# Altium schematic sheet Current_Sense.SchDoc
size 431 x 279 mm; Date: Not shown in title block; ApprovedBy: Not shown in title block; CheckedBy: Not shown in title block; Author: Not shown in title block; CompanyName: Not shown in title block; Engineer: Not shown in title block; Organization: Not shown in title block; Address1: Not shown in title block; Address2: Not shown in title block; Address3: Not shown in title block; Address4: Not shown in title block; DocumentNumber: 1; Revision: Use project parameter SCH_Rev; SheetNumber: 2; SheetTotal: 3; PageSetup: Record=PageOptions¦CenterHorizontal=True¦CenterVertical=True¦PrintScale=1.00¦XCorrection=1.00¦YCorrection=1.00¦PrintKind=0¦BorderSize=5000000¦LeftOffset=0¦BottomOffset=0¦Orientation=2¦PaperLength=1000¦PaperWidth=1000¦Scale=100¦PaperSource=15¦PrintQuality=600¦MediaType=1¦DitherType=10¦PaperKind=Letter¦PrintScaleMode=1
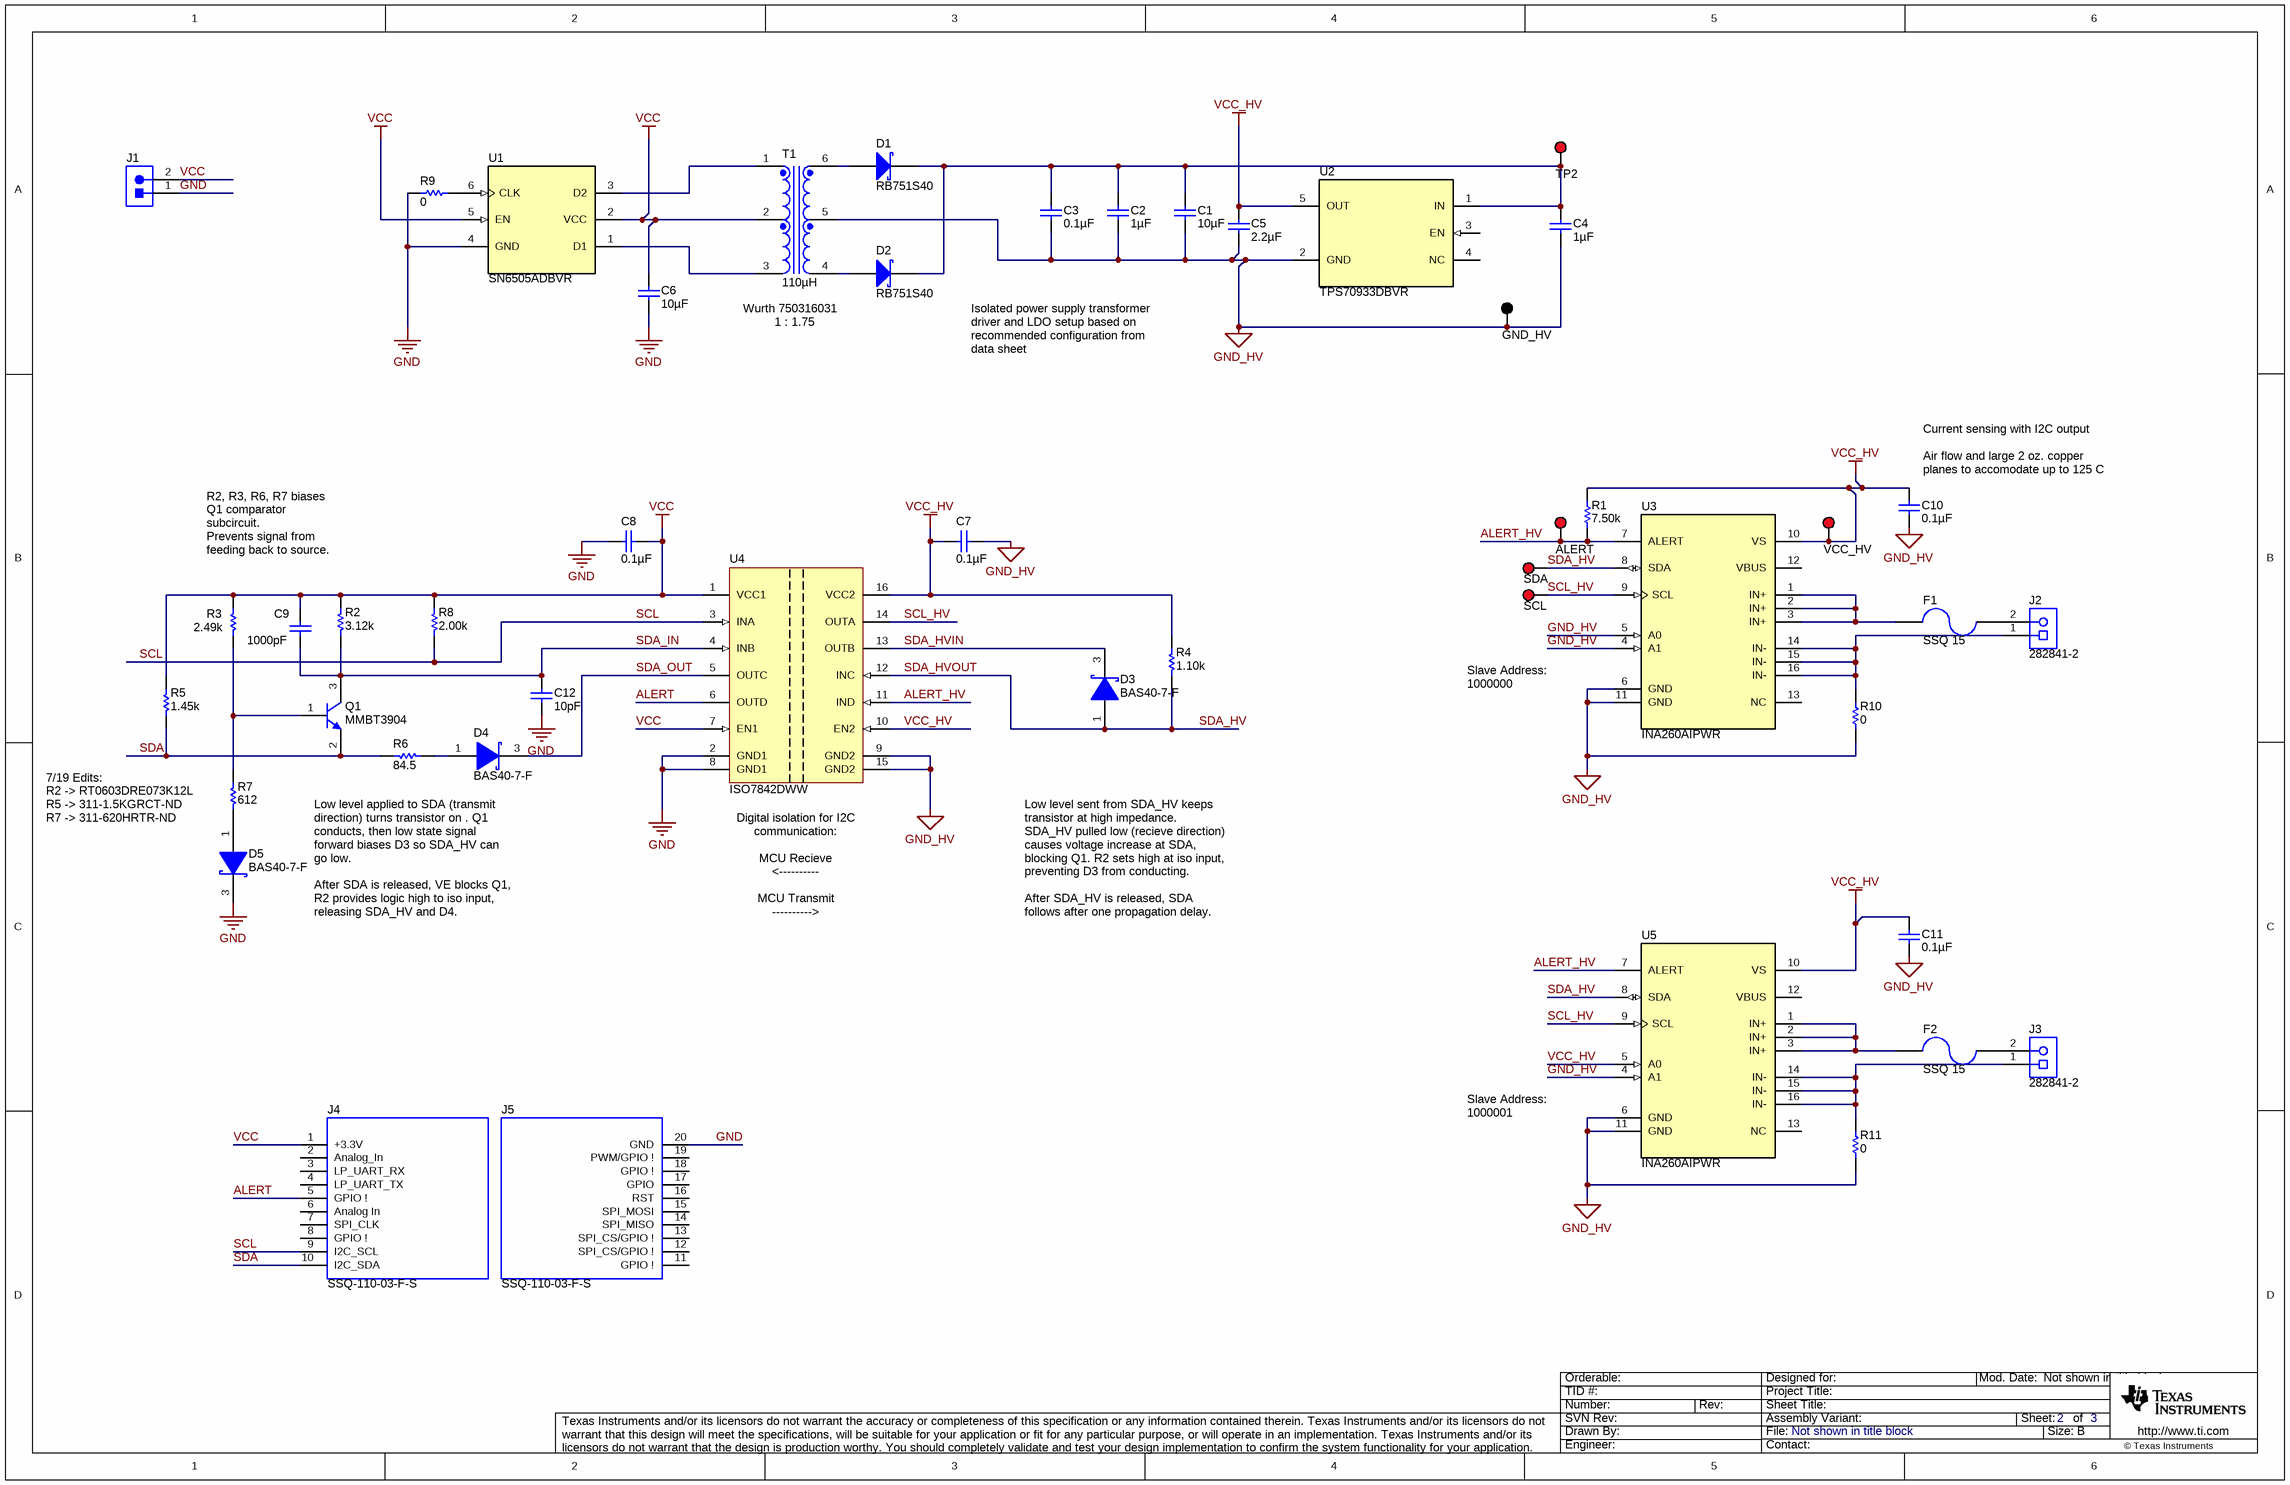
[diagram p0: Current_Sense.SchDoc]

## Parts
ALERT  5000  [Keystone5000]  (value not drawn)
C1  ValueDisplayed: 10µF  [0603]  (hidden comment: GRM188R61C106MAALD)
C2  ValueDisplayed: 1µF  [0603]  (hidden comment: C0603C105K8PACTU)
C3  ValueDisplayed: 0.1µF  [0603]  (hidden comment: GRM188R71C104KA01D)
C4  ValueDisplayed: 1µF  [0603]  (hidden comment: C1608X7R1E105K080AB)
C5  ValueDisplayed: 2.2µF  [0603]  (hidden comment: C1608X7R1A225K080AC)
C6  ValueDisplayed: 10µF  [0603]  (hidden comment: GRM188R61C106MAALD)
C7  ValueDisplayed: 0.1µF  [0603]  (hidden comment: GRM188R71C104KA01D)
C8  ValueDisplayed: 0.1µF  [0603]  (hidden comment: GRM188R71C104KA01D)
C9  ValueDisplayed: 1000pF  [0603]  (hidden comment: 0603ZC102KAT2A)
C10  ValueDisplayed: 0.1µF  [0603]  (hidden comment: GRM188R71C104KA01D)
C11  ValueDisplayed: 0.1µF  [0603]  (hidden comment: GRM188R71C104KA01D)
C12  ValueDisplayed: 10pF  [0603]  (hidden comment: 0603ZC100KAT2A)
D1  RB751S40  [Fairchild_SOD-523F]
D2  RB751S40  [Fairchild_SOD-523F]
D3  BAS40-7-F  [SOT-23]
D4  BAS40-7-F  [SOT-23]
D5  BAS40-7-F  [SOT-23]
F1  SSQ 15  [Fuse_SSQ]
F2  SSQ 15  [Fuse_SSQ]
GND_HV  5001  [Keystone5001]  (value not drawn)
J1  800-10-002-10-001000  [Mill-Max_800-10-002-10-001000]  (value not drawn)
J2  282841-2  [TEC_282841-2]
J3  282841-2  [TEC_282841-2]
J4  SSQ-110-03-F-S  [BoosterPack_20pin_J1]
J5  SSQ-110-03-F-S  [BoosterPack_20pin_J2]
Q1  MMBT3904  [SOT-23]
R1  ValueDisplayed: 7.50k  [0603]  (hidden comment: RC0603FR-077K5L)
R2  ValueDisplayed: 3.12k  [0603]  (hidden comment: RT0603BRD073K12L)
R3  ValueDisplayed: 2.49k  [0603]  (hidden comment: RT0603BRD072K49L)
R4  ValueDisplayed: 1.10k  [0603]  (hidden comment: RT0603BRD071K1L)
R5  ValueDisplayed: 1.45k  [0603]  (hidden comment: RT0603BRD071K45L)
R6  ValueDisplayed: 84.5  [0603]  (hidden comment: RT0603BRD0784R5L)
R7  ValueDisplayed: 612  [0603]  (hidden comment: RT0603BRD07612RL)
R8  ValueDisplayed: 2.00k  [0603]  (hidden comment: RT0603BRD072KL)
R9  ValueDisplayed: 0  [0603]  (hidden comment: CRCW06030000Z0EA)
R10  ValueDisplayed: 0  [0603]  (hidden comment: CRCW06030000Z0EA)
R11  ValueDisplayed: 0  [0603]  (hidden comment: CRCW06030000Z0EA)
SCL  5000  [Keystone5000]  (value not drawn)
SDA  5000  [Keystone5000]  (value not drawn)
T1  ValueDisplayed: 110µH  [Wurth_750315240]  (hidden comment: 750315240)
TP2  5000  [Keystone5000]  (value not drawn)
U1  SN6505ADBVR  [DBV0006A_N]
U2  TPS70933DBVR  [DBV0005A_N]
U3  INA260AIPWR  [PW0016A_N]
U4  ISO7842DWW  [DWW0016A_L]
U5  INA260AIPWR  [PW0016A_N]
VCC_HV  5000  [Keystone5000]  (value not drawn)

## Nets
GND: C6.2 C8.2 C12.2 D5.3(K) J1.1 J5.20(GND) R9.2 U1.4(GND) U4.2(GND1) U4.8(GND1)
GND_HV: C1.2 C2.1 C3.2 C4.2 C5.2 C7.1 C10.2 C11.2 GND_HV.1 R10.2 R11.2 T1.5 U2.2(GND) U3.4(A1) U3.5(A0) U3.6(GND) U3.11(GND) U4.9(GND2) U4.15(GND2) U5.4(A1) U5.6(GND) U5.11(GND)
VCC: C6.1 C8.1 C9.1 J1.2 J4.1(+3.3V) R2.1 R3.2 R5.2 R8.2 T1.2 U1.2(VCC) U1.5(EN) U4.1(VCC1) U4.7(EN1)
VCC_HV: C5.1 C7.2 C10.1 C11.1 R1.2 R4.2 U2.5(OUT) U3.10(VS) U4.10(EN2) U4.16(VCC2) U5.5(A0) U5.10(VS) VCC_HV.1
ALERT: J4.5(GPIO_!) U4.6(OUTD)
ALERT_HV: ALERT.1 R1.1 U3.7(ALERT) U4.11(IND) U5.7(ALERT)
SCL: J4.9(I2C_SCL) R8.1 U4.3(INA)
SCL_HV: SCL.1 U3.9(SCL) U4.14(OUTA) U5.9(SCL)
SDA: J4.10(I2C_SDA) Q1.2(E) R5.1 R6.2
SDA_HV: D3.1(A) R4.1 SDA.1 U3.8(SDA) U4.12(INC) U5.8(SDA)  [also labelled SDA_HVOUT]
SDA_HVIN: D3.3(K) U4.13(OUTB)
SDA_IN: C9.2 C12.1 Q1.3(C) R2.2 U4.4(INB)
SDA_OUT: D4.3(K) U4.5(OUTC)
NetC1_1: C1.1 C2.2 C3.1 C4.1 D1.1(K) D2.1(K) TP2.1 U2.1(IN)
NetD1_2: D1.2(A) T1.6
NetD2_2: D2.2(A) T1.4
NetD4_1: D4.1(A) R6.1
NetD5_1: D5.1(A) R7.1
NetF1_1: F1.1 J2.2
NetF1_2: F1.2 U3.1(IN+) U3.2(IN+) U3.3(IN+)
NetF2_1: F2.1 J3.2
NetF2_2: F2.2 U5.1(IN+) U5.2(IN+) U5.3(IN+)
NetJ2_1: J2.1 R10.1 U3.14(IN-) U3.15(IN-) U3.16(IN-)
NetJ3_1: J3.1 R11.1 U5.14(IN-) U5.15(IN-) U5.16(IN-)
NetQ1_1: Q1.1(B) R3.1 R7.2
NetR9_1: R9.1 U1.6(CLK)
NetT1_1: T1.1 U1.3(D2)
NetT1_3: T1.3 U1.1(D1)

Not connected (* = marked no-connect by the designer): J4 2(Analog_In) 3(LP_UART_RX) 4(LP_UART_TX) 6(Analog_In) 7(SPI_CLK) 8(GPIO_!); J5 11(GPIO_!) 12(SPI_CS/GPIO_!) 13(SPI_CS/GPIO_!) 14(SPI_MISO) 15(SPI_MOSI) 16(RST) 17(GPIO) 18(GPIO_!) 19(PWM/GPIO_!); U2 3(EN) 4(NC); U3 12(VBUS) 13(NC); U5 12(VBUS) 13(NC)

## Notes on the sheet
- Wurth 750316031
  1 : 1.75
- Isolated power supply transformer driver and LDO setup based on recommended configuration from data sheet
- (near C10) Current sensing with I2C output
  Air flow and large 2 oz. copper planes to accomodate up to 125 C
- R2, R3, R6, R7 biases Q1 comparator subcircuit.
  Prevents signal from feeding back to source.
- Slave Address:
  1000000
- 7/19 Edits:
  R2 -> RT0603DRE073K12L
  R5 -> 311-1.5KGRCT-ND
  R7 -> 311-620HRTR-ND
- Low level applied to SDA (transmit direction) turns transistor on . Q1 conducts, then low state signal forward biases D3 so SDA_HV can go low.
  After SDA is released, VE blocks Q1, R2 provides logic high to iso input, releasing SDA_HV and D4.
- (near U4) Digital isolation for I2C communication:
  MCU Recieve
  <----------
  MCU Transmit
  ---------->
- Low level sent from SDA_HV keeps transistor at high impedance. SDA_HV pulled low (recieve direction) causes voltage increase at SDA, blocking Q1. R2 sets high at iso input, preventing D3 from conducting.
  After SDA_HV is released, SDA follows after one propagation delay.
- Slave Address:
  1000001

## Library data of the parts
ALERT SCL SDA TP2 VCC_HV = 5000: Test Point, Miniature, Red, TH; Manufacturer: Keystone; CompType: Test Point Loop; ContactFinish: Silver; Green_Lifecycle: Active; Green_REACh: Passed
C1 C6 = GRM188R61C106MAALD: CAP, CERM, 10 µF, 16 V, +/- 20%, X5R, 0603; Manufacturer: MuRata; Polarized: N; CompType: Capacitor; Value: 10uF; U/M: EA; Cap_F: 0.00001; Tolerance_%: 20; Value1: Unknown; VDC_V: 16; Value2: 16V; TaMin_C: -55; TaMax_C: 85; SizeArea_mm2: 1.28; SizeAreaWB_mm2: 4.68; SizeX_mm: 1.6; SizeY_mm: 0.8; SizeZ_mm: 1; AEC Category: Q200; Green_Lifecycle: Active; Green_REACh: Passed
C2 = C0603C105K8PACTU: CAP, CERM, 1 µF, 10 V, +/- 10%, X5R, 0603; Manufacturer: Kemet; Polarized: N; CompType: Capacitor; Value: 1uF; U/M: EA; Cap_F: 0.000001; Tolerance_%: 10; Value1: Unknown; Value2: 10V; TaMin_C: -55; TaMax_C: 85; SizeArea_mm2: 1.28; SizeAreaWB_mm2: 4.68; SizeX_mm: 1.6; SizeY_mm: 0.8; SizeZ_mm: 1; AEC Category: Q200; Green_Lifecycle: Active; Green_REACh: Passed
C3 C7 C8 C10 C11 = GRM188R71C104KA01D: CAP, CERM, 0.1 µF, 16 V, +/- 10%, X7R, 0603; Manufacturer: MuRata; Polarized: N; CompType: Capacitor; Value: 0.1uF; U/M: EA; Cap_F: 0.0000001; Tolerance_%: 10; Value1: Unknown; VDC_V: 16; Value2: 16V; TaMin_C: -55; TaMax_C: 125; SizeArea_mm2: 1.28; SizeAreaWB_mm2: 4.68; SizeX_mm: 1.6; SizeY_mm: 0.8; SizeZ_mm: 1; AEC Category: Q200; Green_Lifecycle: Active; Green_REACh: Passed
C4 = C1608X7R1E105K080AB: CAP, CERM, 1 µF, 25 V, +/- 10%, X7R, 0603; Manufacturer: TDK; Polarized: N; CompType: Capacitor; Value: 1uF; U/M: EA; Cap_F: 0.000001; Tolerance_%: 10; Value1: Unknown; VDC_V: 25; Value2: 25V; TaMin_C: -55; TaMax_C: 125; SizeArea_mm2: 1.28; SizeAreaWB_mm2: 4.68; SizeX_mm: 1.6; SizeY_mm: 0.8; SizeZ_mm: 1; AEC Category: Q200; Green_Lifecycle: Active; Green_REACh: Passed
C5 = C1608X7R1A225K080AC: CAP, CERM, 2.2 µF, 10 V, +/- 10%, X7R, 0603; Manufacturer: TDK; Polarized: N; CompType: Capacitor; Value: 2.2uF; U/M: EA; Cap_F: 0.0000022; Tolerance_%: 10; ESR_ohm: 0.004058; Value1: 0.004058 ohm; Value2: 10V; IRMS_A: 2.58266; TaMin_C: -55; TaMax_C: 125; SizeArea_mm2: 1.28; SizeAreaWB_mm2: 4.68; SizeX_mm: 1.6; SizeY_mm: 0.8; SizeZ_mm: 1; AEC Category: Q200; Green_Lifecycle: Active; Green_REACh: Passed
C9 = 0603ZC102KAT2A: CAP, CERM, 1000 pF, 10 V, +/- 10%, X7R, 0603; Manufacturer: AVX; Polarized: N; CompType: Capacitor; Value: 1000pF; U/M: EA; Cap_F: 0.000000001; Tolerance_%: 10; Value1: Unknown; Value2: 10V; TaMin_C: -55; TaMax_C: 125; SizeArea_mm2: 1.28; SizeAreaWB_mm2: 4.68; SizeX_mm: 1.6; SizeY_mm: 0.8; SizeZ_mm: 1; AEC Category: Q200
C12 = 0603ZC100KAT2A: CAP, CERM, 10 pF, 10 V, +/- 10%, X7R, 0603; Manufacturer: AVX; Polarized: N; CompType: Capacitor; Value: 10pF; U/M: EA; Cap_F: 0.00000000001; Tolerance_%: 10; Value1: Unknown; Value2: 10V; TaMin_C: -55; TaMax_C: 125; SizeArea_mm2: 1.28; SizeAreaWB_mm2: 4.68; SizeX_mm: 1.6; SizeY_mm: 0.8; SizeZ_mm: 1; AEC Category: Q200
D1 D2 = RB751S40: Diode, Schottky, 40 V, 0.03 A, SOD-523F; Manufacturer: Fairchild Semiconductor; U/M: EA; Vf_V: 0.37; Value: 40V; Value1: 0.03A; Value2: 0.37V; Io_A: 0.03; Vr_V: 40; TJmax_C: 125; SizeAreaWB_mm2: 4.68; SizeArea_mm2: 1.28; SizeX_mm: 1.6; SizeY_mm: 0.8; SizeZ_mm: 0.7; AEC Category: Q101; AEC Qualified: N; Green_Lifecycle: Not Set; Green_REACh: Incomplete
D3-D5 = BAS40-7-F: Diode, Schottky, 40 V, 0.2 A, SOT-23; Manufacturer: Diodes Inc.; U/M: EA; Vf_V: 0.8; Value: 40V; Value1: 0.2A; Value2: 0.8V; Io_A: 0.2; Vr_V: 40; SizeAreaWB_mm2: 14; SizeArea_mm2: 7.5; SizeX_mm: 2.5; SizeY_mm: 3; SizeZ_mm: 1.1; AEC Category: Q101; Green_Lifecycle: Not Set; Green_REACh: Incomplete
F1 F2 = SSQ 15: Fuse, 15 A, SMD; Manufacturer: Bel Fuse; Irating_A: 15; Rtyp_Ohm: 0.004
GND_HV = 5001: Test Point, Miniature, Black, TH; Manufacturer: Keystone; CompType: Test Point Loop; ContactFinish: Silver; Green_Lifecycle: Active; Green_REACh: Passed
J1 = 800-10-002-10-001000: Header, 100mil, 2x1, TH; Manufacturer: Mill-Max; SymbolCreator: a0412235
J2 J3 = 282841-2: Terminal Block, 2x1, 5.08mm, TH; Manufacturer: TE Connectivity; SymbolCreator: a0412235; Green_Lifecycle: Active; Green_REACh: Passed
J4 = BoosterPack_20pin_J1: Receptacle, 2.54mm, 10x1, Gold, TH; Manufacturer: Samtec; Alternate Manufacturer: Major League Electronics; Alternate PartNumber: SSHQ-110-S-08-G-LF; SymbolCreator: a0412235; Note: Booster Pack 20 pin J1
J5 = BoosterPack_20pin_J2: Receptacle, 2.54mm, 10x1, Gold, TH; Manufacturer: Samtec; Alternate Manufacturer: Major League Electronics; Alternate PartNumber: SSHQ-110-S-08-G-LF; SymbolCreator: a0412235; Note: Booster Pack 20 pin J2
Q1 = MMBT3904, Fairchild Semiconductor: Transistor, NPN, 40 V, 0.2 A, SOT-23; CompType: BJT; PNP: 0; NPN: 1; Vceo_V: 40; Vcesat1_V: 0.2; Value: 40 V; Value1: 0.2 A; HfeMax: 300; TaMin_C: -55; TaMax_C: 150; SizeAreaWB_mm2: 14; SizeArea_mm2: 7.5; SizeX_mm: 2.5; SizeY_mm: 3; SizeZ_mm: 1.1; U/M: EA; AEC Category: Q101
R1 = RC0603FR-077K5L: RES, 7.50 k, 1%, 0.1 W, 0603; Manufacturer: Yageo America; CompType: Resistor; Value: 7.50k; Res_ohm: 7500; Value_Code: 7k50; Tolerance_%: 1; Power_W: 0.1; Value2: 0.1W; VDC_V: 150; TempCo: 200 ppm/C; SizeArea_mm2: 1.28; SizeX_mm: 1.6; SizeY_mm: 0.8; EIA_Code: E96; U/M: EA; AEC Category: Q200; Green_Lifecycle: Active; Green_REACh: Passed
R2 = RT0603BRD073K12L: RES, 3.12 k, 0.1%, 0.1 W, 0603; Manufacturer: Yageo America; CompType: Resistor; Value: 3.12k; Res_ohm: 3120; Value_Code: 3k12; Tolerance_%: 0.1; Value2: 0.1W; VDC_V: 75; TempCo: 25 ppm/C; SizeArea_mm2: 1.28; SizeX_mm: 1.6; SizeY_mm: 0.8; SizeZ_mm: 1; EIA_Code: E192; U/M: EA; AEC Category: Q200
R3 = RT0603BRD072K49L: RES, 2.49 k, 0.1%, 0.1 W, 0603; Manufacturer: Yageo America; CompType: Resistor; Value: 2.49k; Res_ohm: 2490; Value_Code: 2k49; Tolerance_%: 0.1; Value2: 0.1W; VDC_V: 75; TempCo: 25 ppm/C; SizeArea_mm2: 1.28; SizeX_mm: 1.6; SizeY_mm: 0.8; SizeZ_mm: 1; EIA_Code: E192; U/M: EA; AEC Category: Q200
R4 = RT0603BRD071K1L: RES, 1.10 k, 0.1%, 0.1 W, 0603; Manufacturer: Yageo America; CompType: Resistor; Value: 1.10k; Res_ohm: 1100; Value_Code: 1k10; Tolerance_%: 0.1; Value2: 0.1W; VDC_V: 75; TempCo: 25 ppm/C; SizeArea_mm2: 1.28; SizeX_mm: 1.6; SizeY_mm: 0.8; SizeZ_mm: 1; EIA_Code: E192; U/M: EA; AEC Category: Q200
R5 = RT0603BRD071K45L: RES, 1.45 k, 0.1%, 0.1 W, 0603; Manufacturer: Yageo America; CompType: Resistor; Value: 1.45k; Res_ohm: 1450; Value_Code: 1k45; Tolerance_%: 0.1; Value2: 0.1W; VDC_V: 75; TempCo: 25 ppm/C; SizeArea_mm2: 1.28; SizeX_mm: 1.6; SizeY_mm: 0.8; SizeZ_mm: 1; EIA_Code: E192; U/M: EA; AEC Category: Q200
R6 = RT0603BRD0784R5L: RES, 84.5, 0.1%, 0.1 W, 0603; Manufacturer: Yageo America; CompType: Resistor; Value: 84.5; Value_Code: 84R5; Tolerance_%: 0.1; Value2: 0.1W; VDC_V: 75; TempCo: 25 ppm/C; SizeArea_mm2: 1.28; SizeX_mm: 1.6; SizeY_mm: 0.8; SizeZ_mm: 1; EIA_Code: E192; U/M: EA; AEC Category: Q200
R7 = RT0603BRD07612RL: RES, 612, 0.1%, 0.1 W, 0603; Manufacturer: Yageo America; CompType: Resistor; Value: 612; Value_Code: 612R; Tolerance_%: 0.1; Value2: 0.1W; VDC_V: 75; TempCo: 25 ppm/C; SizeArea_mm2: 1.28; SizeX_mm: 1.6; SizeY_mm: 0.8; SizeZ_mm: 1; EIA_Code: E192; U/M: EA; AEC Category: Q200
R8 = RT0603BRD072KL: RES, 2.00 k, 0.1%, 0.1 W, 0603; Manufacturer: Yageo America; CompType: Resistor; Value: 2.00k; Res_ohm: 2000; Value_Code: 2k00; Tolerance_%: 0.1; Value2: 0.1W; VDC_V: 75; TempCo: 25 ppm/C; SizeArea_mm2: 1.28; SizeX_mm: 1.6; SizeY_mm: 0.8; SizeZ_mm: 1; EIA_Code: E192; U/M: EA; AEC Category: Q200
R9-R11 = CRCW06030000Z0EA: RES, 0, 5%, 0.1 W, 0603; Manufacturer: Vishay-Dale; CompType: Resistor; Value: 0; Value_Code: 0000; Tolerance_%: 5; Power_W: 0.1; Value2: 0.1W; VDC_V: 75; TempCo: 200 ppm/C; SizeArea_mm2: 1.28; SizeX_mm: 1.6; SizeY_mm: 0.8; SizeZ_mm: 1; EIA_Code: E24; U/M: EA; AEC Category: Q200; Green_Lifecycle: Active; Green_REACh: Passed
T1 = 750315240: Transformer, 110 uH, SMT; Manufacturer: Wurth Elektronik; SymbolCreator: Altium; Value: 110uH; DCR_ohm: 0.15; Lp: 110; Ind_H: 0.00011; Green_Lifecycle: Active; Green_REACh: Passed
U1 = SN6505ADBVR: Low-Noise 1-A Transformer Driver for Isolated Power Supplies, Internal Clock-160kHz, DBV0006A (SOT-23-6); Alternate PartNumber: SN6505ADBVT; Manufacturer: Texas Instruments; SymbolCreator: Altium; SizeArea_mm2: 8.12; SizeAreaWB_mm2: 14.82; SizeX_mm: 2.8; SizeY_mm: 2.9; SizeZ_mm: 1.45; CompType: IC; U/M: EA; Green_Lifecycle: Active; Green_REACh: Passed
U2 = TPS70933DBVR: 150-mA, 30-V, Ultra-Low IQ, Wide Input Low-Dropout Regulator with Reverse Current Protection, DBV0005A (SOT-23-5); Alternate PartNumber: TPS70933DBVT; Manufacturer: Texas Instruments; SymbolCreator: Altium; SizeArea_mm2: 8.12; SizeAreaWB_mm2: 14.82; SizeX_mm: 2.8; SizeY_mm: 2.9; SizeZ_mm: 1.45; CompType: IC; U/M: EA; Green_Lifecycle: Active; Green_REACh: Passed
U3 U5 = INA260AIPWR: Integrated Shunt High-Side or Low-Side Measurement, Bi-Directional Current and Power Monitor with I2C Compatible Interface, PW0016A (TSSOP-16); Manufacturer: Texas Instruments; SymbolCreator: Altium; SizeArea_mm2: 32; SizeAreaWB_mm2: 58.8; SizeX_mm: 6.4; SizeY_mm: 5; SizeZ_mm: 1.2; CompType: IC; U/M: EA
U4 = ISO7842DWW: 5.7 kVrms, 100 Mbps, Reinforced 4-Channel 2/2 Digital Isolator, DWW0016A (SOIC-16); Manufacturer: Texas Instruments; SymbolCreator: Altium; SizeArea_mm2: 183.855; SizeAreaWB_mm2: 244.155; SizeX_mm: 17.85; SizeY_mm: 10.3; SizeZ_mm: 2.65; CompType: IC; U/M: EA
